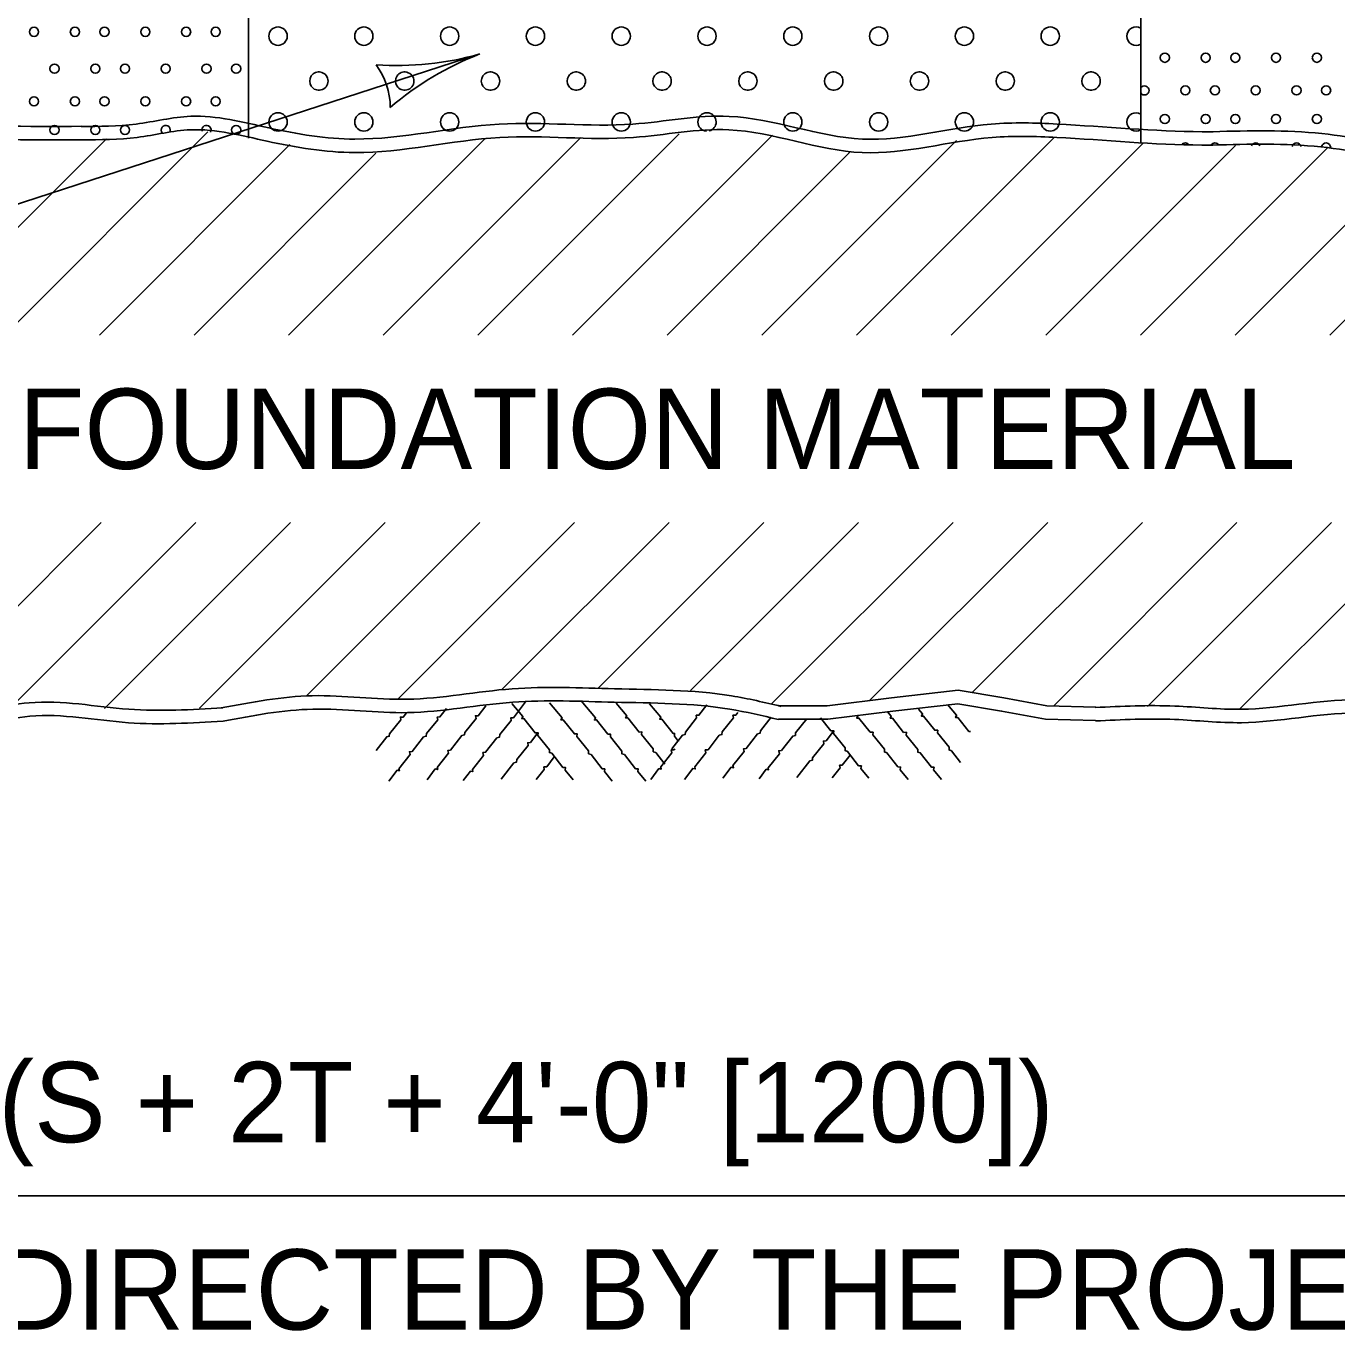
# Model space of a CAD drawing. Extents: x 49991.4 to 50021, y 49987.6 to 50011.4.
# Drawn here: x 50008.745 to 50009.724, y 49988.853 to 49989.828 of the extents above; entities that cross this region are included whole.
import ezdxf

# ---------------------------------------------------------------- set-up
doc = ezdxf.new("R2010")
doc.units = 0
for name, color, linetype in [('Level 1', 7, 'Continuous'), ('Level 2', 7, 'Continuous'), ('Level 3', 7, 'Continuous')]:
    doc.layers.add(name, color=color, linetype=linetype)

msp = doc.modelspace()

# ---------------------------------------------------------------- linework, layer by layer
at = {"layer": 'Level 1'}
for p, q in [((50008.91081, 49989.8661), (50008.91081, 49989.74418)), ((50009.57749, 49989.86595), (50009.57749, 49989.74087)), ((50008.72876, 49989.59715), (50008.88051, 49989.7489)), ((50009.08232, 49989.59715), (50009.23263, 49989.74745)), ((50008.38558, 49989.32467), (50008.80474, 49989.74384)), ((50008.79947, 49989.59715), (50008.94189, 49989.73956)), ((50008.9409, 49989.59715), (50009.0879, 49989.74415)), ((50009.01161, 49989.59715), (50009.15915, 49989.74469)), ((50009.15303, 49989.59715), (50009.30231, 49989.74643)), ((50009.29445, 49989.59715), (50009.4399, 49989.7426)), ((50009.36517, 49989.59715), (50009.51287, 49989.74485)), ((50009.43588, 49989.59715), (50009.57947, 49989.74074)), ((50009.50659, 49989.59715), (50009.64822, 49989.73878)), ((50009.5773, 49989.59715), (50009.71761, 49989.73745)), ((50008.87019, 49989.59715), (50009.00603, 49989.733)), ((50009.22374, 49989.59715), (50009.3603, 49989.73371)), ((50009.64801, 49989.59715), (50009.77934, 49989.72847)), ((50009.71872, 49989.59715), (50009.85635, 49989.73477)), ((50008.65998, 49989.31623), (50008.8009, 49989.45715)), ((50008.73617, 49989.32171), (50008.87161, 49989.45715)), ((50008.80327, 49989.31809), (50008.94232, 49989.45715)), ((50008.87427, 49989.31839), (50009.01303, 49989.45715)), ((50008.95422, 49989.32763), (50009.08374, 49989.45715)), ((50009.02228, 49989.32497), (50009.15445, 49989.45715)), ((50009.10028, 49989.33226), (50009.22516, 49989.45715)), ((50009.17187, 49989.33314), (50009.29588, 49989.45715)), ((50009.24108, 49989.33164), (50009.36659, 49989.45715)), ((50009.30169, 49989.32154), (50009.4373, 49989.45715)), ((50009.37515, 49989.32428), (50009.50801, 49989.45715)), ((50009.45182, 49989.33025), (50009.57872, 49989.45715)), ((50009.51256, 49989.32028), (50009.64943, 49989.45715)), ((50009.5826, 49989.3196), (50009.72015, 49989.45715)), ((50009.65133, 49989.31762), (50009.79086, 49989.45715))]:
    msp.add_line(p, q, dxfattribs=at)
for points in [[(50009.30677, 49989.32028), (50009.34316, 49989.32028), (50009.3912, 49989.32611), (50009.44104, 49989.33178), (50009.47528, 49989.32604), (50009.50741, 49989.32026), (50009.54397, 49989.31918)], [(50009.01576, 49989.26378), (50009.02196, 49989.27208), (50009.02366, 49989.27168), (50009.02326, 49989.27318), (50009.03166, 49989.28378), (50009.03116, 49989.28588), (50009.03326, 49989.28608), (50009.04167, 49989.29688), (50009.04367, 49989.29738), (50009.04387, 49989.29938), (50009.05227, 49989.30978), (50009.05197, 49989.31178), (50009.05397, 49989.31188), (50009.05887, 49989.31818)], [(50009.04427, 49989.26478), (50009.05047, 49989.27298), (50009.05227, 49989.27258), (50009.05187, 49989.27418), (50009.06027, 49989.28468), (50009.05977, 49989.28678), (50009.06177, 49989.28698), (50009.07027, 49989.29788), (50009.07217, 49989.29838), (50009.07247, 49989.30028), (50009.08087, 49989.31078), (50009.08047, 49989.31278), (50009.08257, 49989.31278), (50009.08827, 49989.32018)], [(50009.07137, 49989.26428), (50009.07677, 49989.27138), (50009.07847, 49989.27098), (50009.07817, 49989.27258), (50009.08657, 49989.28318), (50009.08607, 49989.28518), (50009.08807, 49989.28548), (50009.09647, 49989.29628), (50009.09847, 49989.29678), (50009.09867, 49989.29878), (50009.10707, 49989.30918), (50009.10677, 49989.31118), (50009.10887, 49989.31128), (50009.11787, 49989.32308)], [(50009.10767, 49989.32188), (50009.11587, 49989.31218), (50009.11507, 49989.31058), (50009.11667, 49989.31058), (50009.12507, 49989.29998), (50009.12727, 49989.30008), (50009.12697, 49989.29808), (50009.13567, 49989.28738), (50009.13567, 49989.28528), (50009.13747, 49989.28468), (50009.14577, 49989.27408), (50009.14777, 49989.27398), (50009.14737, 49989.27198), (50009.15337, 49989.26478)], [(50009.13577, 49989.32248), (50009.14517, 49989.31128), (50009.14437, 49989.30968), (50009.14597, 49989.30968), (50009.15437, 49989.29918), (50009.15657, 49989.29918), (50009.15627, 49989.29718), (50009.16497, 49989.28648), (50009.16497, 49989.28438), (50009.16687, 49989.28378), (50009.17507, 49989.27318), (50009.17707, 49989.27308), (50009.17677, 49989.27108), (50009.18267, 49989.26388)], [(50009.15937, 49989.32398), (50009.17017, 49989.31118), (50009.16937, 49989.30958), (50009.17097, 49989.30958), (50009.17937, 49989.29898), (50009.18147, 49989.29898), (50009.18127, 49989.29698), (50009.18987, 49989.28628), (50009.18987, 49989.28428), (50009.19177, 49989.28368), (50009.20007, 49989.27308), (50009.20207, 49989.27298), (50009.20167, 49989.27098), (50009.20767, 49989.26378)], [(50009.18567, 49989.32208), (50009.19347, 49989.31278), (50009.19267, 49989.31118), (50009.19427, 49989.31118), (50009.20267, 49989.30058), (50009.20487, 49989.30068), (50009.20457, 49989.29868), (50009.21327, 49989.28798), (50009.21327, 49989.28588), (50009.21517, 49989.28528), (50009.22197, 49989.27658)], [(50009.21057, 49989.32168), (50009.21897, 49989.31178), (50009.21817, 49989.31018), (50009.21977, 49989.31018), (50009.22817, 49989.29958), (50009.22927, 49989.29958)], [(50009.22727, 49989.28798), (50009.23507, 49989.29818), (50009.23707, 49989.29868), (50009.23727, 49989.30058), (50009.24567, 49989.31108), (50009.24537, 49989.31308), (50009.24747, 49989.31308), (50009.25337, 49989.32088)], [(50009.30677, 49989.31028), (50009.34377, 49989.31028), (50009.39237, 49989.31618), (50009.44077, 49989.32168), (50009.47357, 49989.31618), (50009.50637, 49989.31028), (50009.54367, 49989.30918)], [(50009.41137, 49989.31778), (50009.41447, 49989.31408), (50009.41367, 49989.31248), (50009.41527, 49989.31248), (50009.42367, 49989.30198), (50009.42587, 49989.30198), (50009.42557, 49989.29998), (50009.43427, 49989.28928), (50009.43427, 49989.28728), (50009.43607, 49989.28658), (50009.44297, 49989.27778)], [(50009.43317, 49989.32108), (50009.43997, 49989.31308), (50009.43917, 49989.31138), (50009.44077, 49989.31148), (50009.44917, 49989.30088), (50009.45027, 49989.30088)], [(50009.00626, 49989.28678), (50009.01416, 49989.29688), (50009.01606, 49989.29738), (50009.01626, 49989.29928), (50009.02466, 49989.30968), (50009.02436, 49989.31178), (50009.02646, 49989.31178), (50009.02886, 49989.31498)], [(50009.23677, 49989.26508), (50009.24287, 49989.27338), (50009.24467, 49989.27298), (50009.24427, 49989.27448), (50009.25267, 49989.28508), (50009.25217, 49989.28718), (50009.25427, 49989.28738), (50009.26267, 49989.29818), (50009.26457, 49989.29868), (50009.26487, 49989.30068), (50009.27327, 49989.31108), (50009.27287, 49989.31308), (50009.27497, 49989.31318), (50009.27647, 49989.31508)], [(50009.26527, 49989.26608), (50009.27147, 49989.27428), (50009.27327, 49989.27388), (50009.27287, 49989.27548), (50009.28127, 49989.28608), (50009.28077, 49989.28808), (50009.28277, 49989.28838), (50009.29127, 49989.29918), (50009.29317, 49989.29968), (50009.29347, 49989.30158), (50009.30147, 49989.31168)], [(50009.29237, 49989.26558), (50009.29777, 49989.27278), (50009.29947, 49989.27238), (50009.29917, 49989.27388), (50009.30757, 49989.28438), (50009.30707, 49989.28658), (50009.30907, 49989.28678), (50009.31747, 49989.29758), (50009.31947, 49989.29808), (50009.31967, 49989.29998), (50009.32807, 49989.31048), (50009.32807, 49989.31058)], [(50009.33827, 49989.31118), (50009.34607, 49989.30138), (50009.34827, 49989.30138), (50009.34797, 49989.29938), (50009.35667, 49989.28868), (50009.35667, 49989.28668), (50009.35847, 49989.28598), (50009.36677, 49989.27538), (50009.36877, 49989.27528), (50009.36837, 49989.27328), (50009.37437, 49989.26608)], [(50009.36577, 49989.31308), (50009.36617, 49989.31258), (50009.36537, 49989.31098), (50009.36697, 49989.31098), (50009.37537, 49989.30048), (50009.37757, 49989.30048), (50009.37727, 49989.29848), (50009.38597, 49989.28778), (50009.38597, 49989.28578), (50009.38787, 49989.28508), (50009.39607, 49989.27448), (50009.39807, 49989.27438), (50009.39767, 49989.27238), (50009.40367, 49989.26518)], [(50009.38837, 49989.31568), (50009.39107, 49989.31248), (50009.39037, 49989.31088), (50009.39197, 49989.31088), (50009.40037, 49989.30028), (50009.40247, 49989.30038), (50009.40227, 49989.29828), (50009.41087, 49989.28758), (50009.41087, 49989.28558), (50009.41277, 49989.28498), (50009.42107, 49989.27438), (50009.42307, 49989.27428), (50009.42267, 49989.27228), (50009.42867, 49989.26508)], [(50009.09957, 49989.26538), (50009.10917, 49989.27768), (50009.11117, 49989.27818), (50009.11137, 49989.28018), (50009.11977, 49989.29058), (50009.11947, 49989.29258), (50009.12157, 49989.29268), (50009.12707, 49989.29998)], [(50009.22827, 49989.29958), (50009.22927, 49989.29958), (50009.22907, 49989.29758), (50009.23227, 49989.29358)], [(50009.32057, 49989.26668), (50009.33017, 49989.27898), (50009.33217, 49989.27948), (50009.33237, 49989.28138), (50009.34077, 49989.29188), (50009.34047, 49989.29388), (50009.34247, 49989.29398), (50009.34807, 49989.30128)], [(50009.21147, 49989.26518), (50009.21757, 49989.27328), (50009.21927, 49989.27288), (50009.21897, 49989.27448), (50009.22727, 49989.28498), (50009.22677, 49989.28718), (50009.22887, 49989.28738), (50009.22937, 49989.28808)], [(50009.12587, 49989.26508), (50009.13187, 49989.27248), (50009.13157, 49989.27448), (50009.13367, 49989.27458), (50009.13937, 49989.28208)], [(50009.34687, 49989.26638), (50009.35287, 49989.27378), (50009.35257, 49989.27578), (50009.35457, 49989.27588), (50009.36037, 49989.28338)]]:
    msp.add_lwpolyline(points, dxfattribs=at)
for centre in [(50008.7507, 49989.82366), (50008.78118, 49989.82366), (50008.80332, 49989.82366), (50008.8338, 49989.82366), (50008.86428, 49989.82366), (50008.88642, 49989.82366), (50009.61079, 49989.77992), (50009.63293, 49989.77992), (50009.66341, 49989.77992), (50009.69389, 49989.77992), (50009.71603, 49989.77992), (50008.7507, 49989.77173), (50008.78118, 49989.77173), (50008.80332, 49989.77173), (50008.8338, 49989.77173), (50008.86428, 49989.77173), (50008.88642, 49989.77173), (50009.59555, 49989.75858), (50009.59555, 49989.75858), (50009.62603, 49989.75858), (50009.64817, 49989.75858), (50009.67865, 49989.75858), (50009.67865, 49989.75858), (50009.70913, 49989.75858), (50008.76594, 49989.75039), (50008.76594, 49989.75039), (50008.79642, 49989.75039), (50008.81856, 49989.75039), (50008.90166, 49989.75039)]:
    msp.add_circle(centre, 0.00341, dxfattribs=at)
for centre, radius, start, end in [((50008.93298, 49989.8205), 0.00682, 0, 180), ((50008.99708, 49989.8205), 0.00682, 0, 180), ((50009.06118, 49989.8205), 0.00682, 0, 180), ((50009.12528, 49989.8205), 0.00682, 0, 180), ((50009.18938, 49989.8205), 0.00682, 0, 180), ((50009.25348, 49989.8205), 0.00682, 0, 180), ((50009.31758, 49989.8205), 0.00682, 0, 180), ((50009.38169, 49989.8205), 0.00682, 0, 180), ((50009.44579, 49989.8205), 0.00682, 0, 180), ((50009.50989, 49989.8205), 0.00682, 0, 180), ((50009.57399, 49989.8205), 0.00682, 59.10946, 180), ((50008.93298, 49989.8204), 0.00682, 180, 0), ((50008.99708, 49989.8204), 0.00682, 180, 0), ((50009.06118, 49989.8204), 0.00682, 180, 0), ((50009.12528, 49989.8204), 0.00682, 180, 0), ((50009.18938, 49989.8204), 0.00682, 180, 0), ((50009.25348, 49989.8204), 0.00682, 180, 0), ((50009.31758, 49989.8204), 0.00682, 180, 0), ((50009.38169, 49989.8204), 0.00682, 180, 0), ((50009.44579, 49989.8204), 0.00682, 180, 0), ((50009.50989, 49989.8204), 0.00682, 180, 0), ((50009.57399, 49989.8204), 0.00682, 180, 300.89054), ((50009.59555, 49989.80441), 0.00341, 0, 180), ((50009.62603, 49989.80441), 0.00341, 0, 180), ((50009.64817, 49989.80441), 0.00341, 0, 180), ((50009.67865, 49989.80441), 0.00341, 0, 180), ((50009.70913, 49989.80441), 0.00341, 0, 180), ((50008.76594, 49989.79623), 0.00341, 0, 180), ((50008.76594, 49989.79611), 0.00341, 180, 0), ((50008.76594, 49989.79611), 0.00341, 180, 0), ((50008.79642, 49989.79623), 0.00341, 0, 180), ((50008.79642, 49989.79611), 0.00341, 180, 0), ((50008.81856, 49989.79623), 0.00341, 0, 180), ((50008.81856, 49989.79611), 0.00341, 180, 0), ((50008.84904, 49989.79623), 0.00341, 0, 180), ((50008.84904, 49989.79611), 0.00341, 180, 0), ((50008.84904, 49989.79611), 0.00341, 180, 0), ((50008.87952, 49989.79623), 0.00341, 0, 180), ((50008.87952, 49989.79611), 0.00341, 180, 0), ((50008.90166, 49989.79623), 0.00341, 0, 180), ((50008.90166, 49989.79611), 0.00341, 180, 0), ((50009.59555, 49989.8043), 0.00341, 180, 0), ((50009.59555, 49989.8043), 0.00341, 180, 0), ((50009.62603, 49989.8043), 0.00341, 180, 0), ((50009.64817, 49989.8043), 0.00341, 180, 0), ((50009.67865, 49989.8043), 0.00341, 180, 0), ((50009.67865, 49989.8043), 0.00341, 180, 0), ((50009.70913, 49989.8043), 0.00341, 180, 0), ((50008.96346, 49989.78688), 0.00682, 77.07903, 282.92097), ((50008.96355, 49989.78688), 0.00682, 282.92097, 77.07903), ((50009.02756, 49989.78688), 0.00682, 77.07903, 282.92097), ((50009.02765, 49989.78688), 0.00682, 282.92097, 77.07903), ((50009.09166, 49989.78688), 0.00682, 77.07903, 282.92097), ((50009.09175, 49989.78688), 0.00682, 282.92097, 77.07903), ((50009.15576, 49989.78688), 0.00682, 77.07903, 282.92097), ((50009.15585, 49989.78688), 0.00682, 282.92097, 77.07903), ((50009.21986, 49989.78688), 0.00682, 77.07903, 282.92097), ((50009.21996, 49989.78688), 0.00682, 282.92097, 77.07903), ((50009.28396, 49989.78688), 0.00682, 77.07903, 282.92097), ((50009.28406, 49989.78688), 0.00682, 282.92097, 77.07903), ((50009.34807, 49989.78688), 0.00682, 77.07903, 282.92097), ((50009.34816, 49989.78688), 0.00682, 282.92097, 77.07903), ((50009.41217, 49989.78688), 0.00682, 77.07903, 282.92097), ((50009.41226, 49989.78688), 0.00682, 282.92097, 77.07903), ((50009.47627, 49989.78688), 0.00682, 77.07903, 282.92097), ((50009.47636, 49989.78688), 0.00682, 282.92097, 77.07903), ((50009.54037, 49989.78688), 0.00682, 77.07903, 282.92097), ((50009.54046, 49989.78688), 0.00682, 282.92097, 77.07903), ((50009.58031, 49989.77992), 0.00341, 214.20217, 145.79783), ((50008.93298, 49989.7564), 0.00682, 0, 180), ((50008.99708, 49989.7564), 0.00682, 0, 180), ((50009.06118, 49989.7564), 0.00682, 0, 180), ((50009.12528, 49989.7564), 0.00682, 0, 180), ((50009.18938, 49989.7564), 0.00682, 0, 180), ((50009.25348, 49989.7564), 0.00682, 0, 180), ((50009.31758, 49989.7564), 0.00682, 0, 180), ((50009.38169, 49989.7564), 0.00682, 0, 180), ((50009.44579, 49989.7564), 0.00682, 0, 180), ((50009.50989, 49989.7564), 0.00682, 0, 180), ((50009.57399, 49989.7564), 0.00682, 59.10946, 180), ((50008.84904, 49989.75039), 0.00341, 342.61051, 222.9149), ((50008.84904, 49989.75039), 0.00341, 342.61051, 222.9149), ((50008.87952, 49989.75039), 0.00341, 328.9106, 195.53658), ((50008.93298, 49989.7563), 0.00682, 180, 0), ((50008.99708, 49989.7563), 0.00682, 180, 0), ((50009.06118, 49989.7563), 0.00682, 180, 0), ((50009.12528, 49989.7563), 0.00682, 180, 0), ((50009.18938, 49989.7563), 0.00682, 180, 0), ((50009.25348, 49989.7563), 0.00682, 180, 265.65276), ((50009.25348, 49989.7563), 0.00682, 284.20444, 0), ((50009.31758, 49989.7563), 0.00682, 180, 0), ((50009.38169, 49989.7563), 0.00682, 180, 0), ((50009.44579, 49989.7563), 0.00682, 180, 0), ((50009.50989, 49989.7563), 0.00682, 180, 0), ((50009.57399, 49989.7563), 0.00682, 180, 300.89054), ((50009.61079, 49989.73724), 0.00341, 34.57719, 142.74868), ((50009.63293, 49989.73724), 0.00341, 30.99053, 147.37352), ((50009.66341, 49989.73724), 0.00341, 20.95427, 157.09938), ((50009.69389, 49989.73724), 0.00341, 11.85612, 166.1848), ((50009.71603, 49989.73724), 0.00341, 1.5478, 172.77086)]:
    msp.add_arc(centre, radius, start, end, dxfattribs=at)
for points in [[(50008.7863, 49989.75308), (50008.66459, 49989.75478), (50008.5905, 49989.75719), (50008.51677, 49989.75248), (50008.4242, 49989.75298)], [(50009.63147, 49989.74908), (50009.62353, 49989.74908), (50009.51513, 49989.75478), (50009.46589, 49989.75478), (50009.36974, 49989.74358), (50009.27012, 49989.76055), (50009.19807, 49989.75478), (50009.09815, 49989.75478), (50008.99039, 49989.74355), (50008.92614, 49989.75189), (50008.86769, 49989.76059), (50008.82685, 49989.75475), (50008.78575, 49989.75307)], [(50008.78616, 49989.74308), (50008.66436, 49989.74478), (50008.59066, 49989.74718), (50008.51706, 49989.74248), (50008.42416, 49989.74298)], [(50009.63147, 49989.73908), (50009.62327, 49989.73908), (50009.51487, 49989.74478), (50009.46647, 49989.74478), (50009.36947, 49989.73348), (50009.26967, 49989.75048), (50009.19847, 49989.74478), (50009.09867, 49989.74478), (50008.99026, 49989.73348), (50008.92476, 49989.74198), (50008.86766, 49989.75048), (50008.82776, 49989.74478), (50008.78616, 49989.74308)], [(50010.00195, 49989.74908), (50009.89468, 49989.74768), (50009.78608, 49989.73834), (50009.71289, 49989.74767), (50009.63155, 49989.74908)], [(50010.00208, 49989.73908), (50009.89517, 49989.73768), (50009.78587, 49989.72828), (50009.71217, 49989.73768), (50009.63137, 49989.73908)], [(50008.89054, 49989.31859), (50008.95858, 49989.32771), (50009.02945, 49989.3251), (50009.10777, 49989.33288), (50009.18437, 49989.33288), (50009.27181, 49989.32762), (50009.30884, 49989.31977)], [(50008.5307, 49989.31867), (50008.61245, 49989.32241), (50008.68789, 49989.31298), (50008.74699, 49989.32243), (50008.82141, 49989.31759), (50008.8917, 49989.31868)], [(50008.89186, 49989.30868), (50008.95906, 49989.31768), (50009.02976, 49989.31508), (50009.10827, 49989.32288), (50009.18407, 49989.32288), (50009.27047, 49989.31768), (50009.30677, 49989.30998)], [(50009.54348, 49989.31888), (50009.60302, 49989.31999), (50009.6526, 49989.3176), (50009.73846, 49989.32472), (50009.81, 49989.31759), (50009.90474, 49989.31888)], [(50008.53116, 49989.30868), (50008.61206, 49989.31238), (50008.68806, 49989.30288), (50008.74746, 49989.31238), (50008.82116, 49989.30758), (50008.89186, 49989.30868)], [(50009.54367, 49989.30888), (50009.60287, 49989.30998), (50009.65277, 49989.30758), (50009.73837, 49989.31468), (50009.80957, 49989.30758), (50009.90487, 49989.30888)]]:
    msp.add_spline(points, degree=3, dxfattribs=at)
at = {"layer": 'Level 3'}
for p, q in [((50008.07812, 49989.48071), (50009.08374, 49989.80713)), ((50010.24066, 49988.95414), (50008.26777, 49988.95414))]:
    msp.add_line(p, q, dxfattribs=at)
for centre, radius, start, end in [((50009.02253, 49990.02086), 0.22232, 265.79822, 285.98173), ((50009.16789, 49989.58986), 0.233, 111.16952, 130.41937), ((50008.96204, 49989.76678), 0.05478, 0.48103, 36.20339)]:
    msp.add_arc(centre, radius, start, end, dxfattribs=at)

# ---------------------------------------------------------------- texts
at = {"layer": 'Level 2'}
for s, p in [('FOUNDATION MATERIAL', (50008.7393, 49989.49715)), ('(S + 2T + 4\'-0" [1200])', (50008.72397, 49988.99414)), ('OR AS DIRECTED BY THE PROJECT', (50008.45254, 49988.85414))]:
    msp.add_text(s, height=0.06, dxfattribs=at).set_placement(p)

doc.saveas('drawing.dxf')
